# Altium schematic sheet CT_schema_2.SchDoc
size 379 x 215 mm
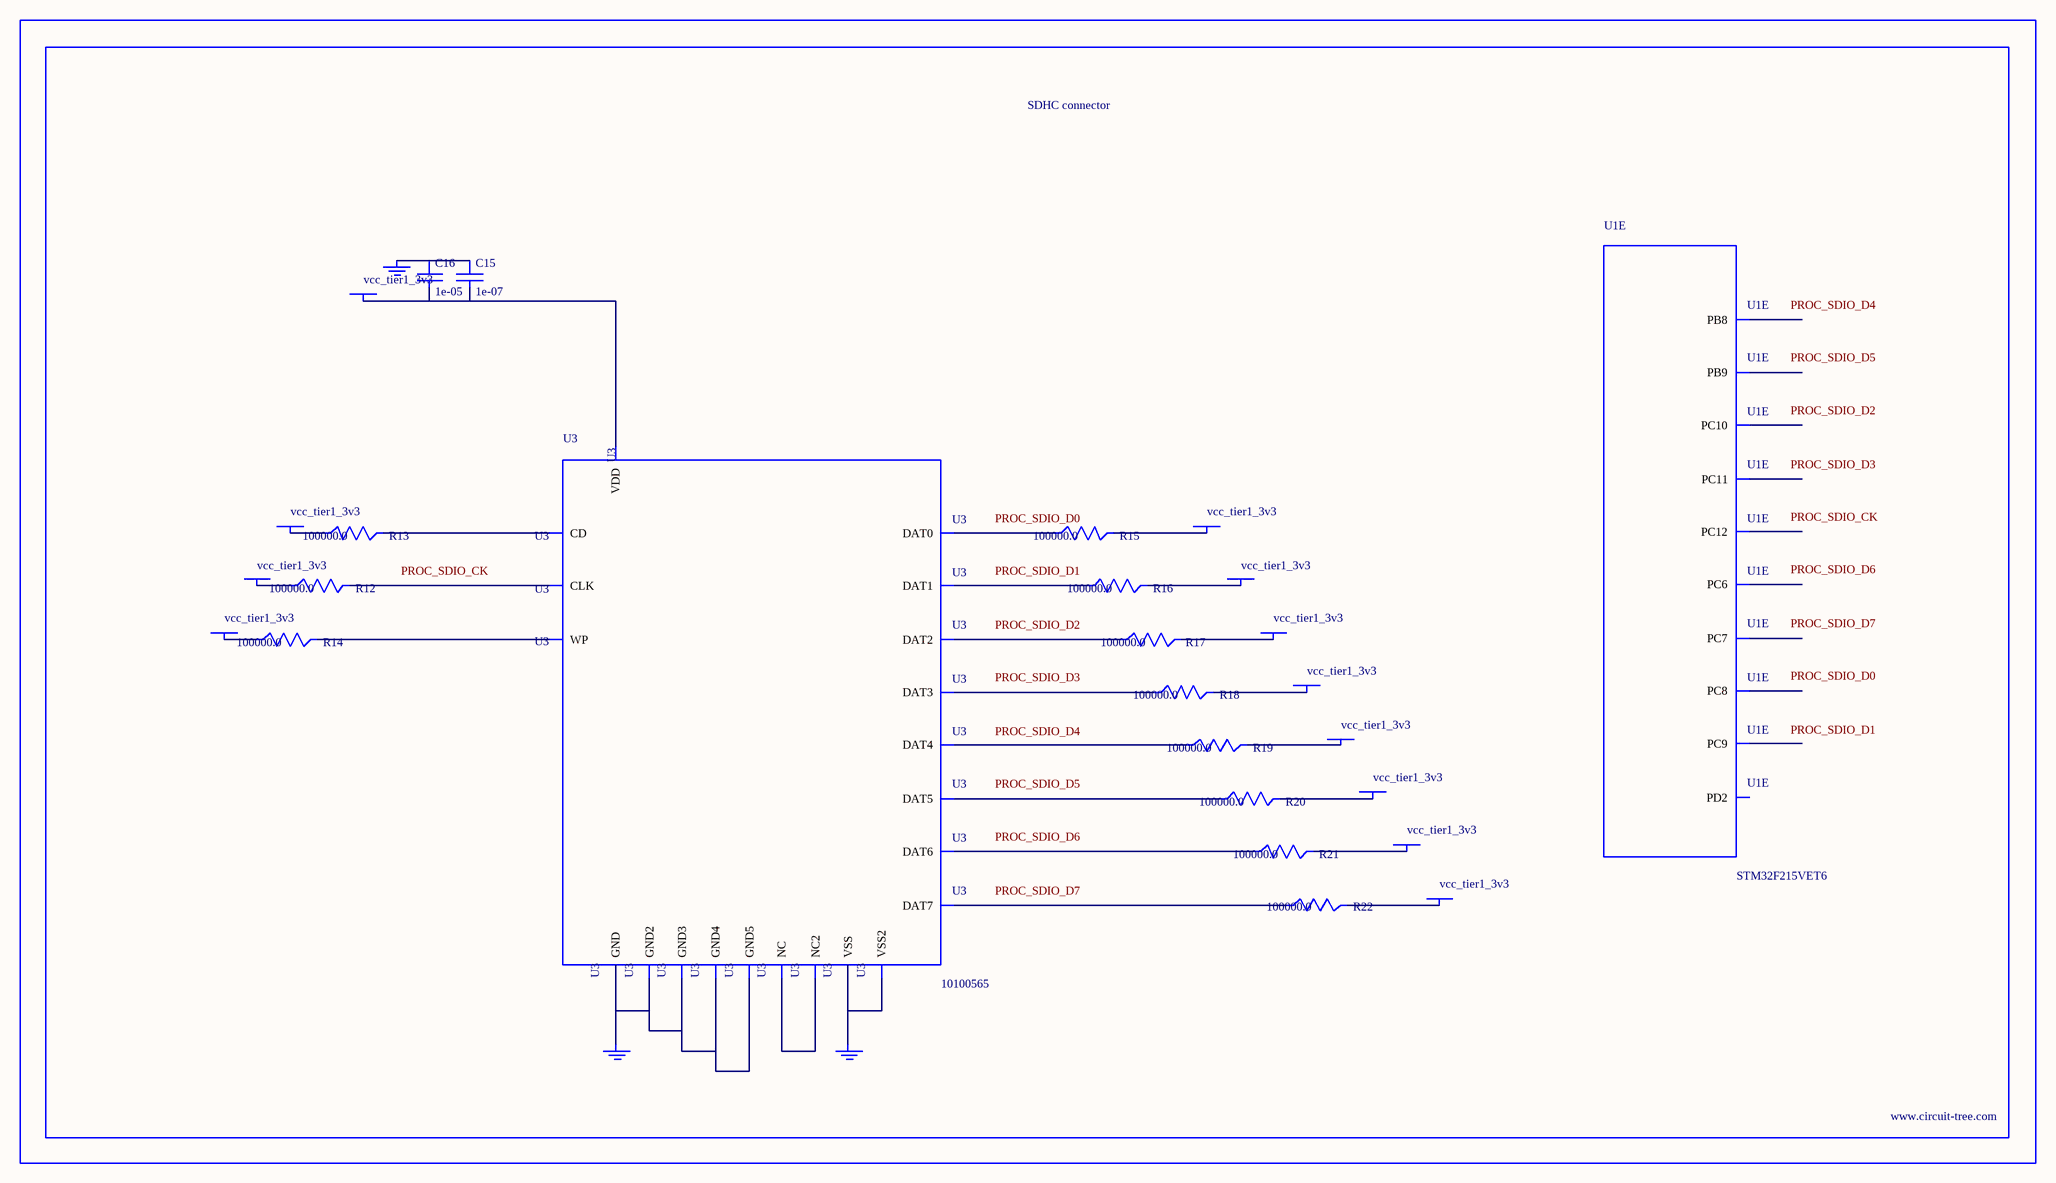
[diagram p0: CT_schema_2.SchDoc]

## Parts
BORDER1  (no value)
C15  1e-07  [C0402]
C16  1e-05  [C0805]
GND_INSTANCE_1_0  (no value)
GND_INSTANCE_1_1  (no value)
GND_INSTANCE_1_2  (no value)
POWER_INSTANCE_1_0  vcc_tier1_3v3
POWER_INSTANCE_1_1  vcc_tier1_3v3
POWER_INSTANCE_1_2  vcc_tier1_3v3
POWER_INSTANCE_1_3  vcc_tier1_3v3
POWER_INSTANCE_1_4  vcc_tier1_3v3
POWER_INSTANCE_1_5  vcc_tier1_3v3
POWER_INSTANCE_1_6  vcc_tier1_3v3
POWER_INSTANCE_1_7  vcc_tier1_3v3
POWER_INSTANCE_1_8  vcc_tier1_3v3
POWER_INSTANCE_1_9  vcc_tier1_3v3
POWER_INSTANCE_1_10  vcc_tier1_3v3
POWER_INSTANCE_1_11  vcc_tier1_3v3
R12  100000.0  [R0603]
R13  100000.0  [R0603]
R14  100000.0  [R0603]
R15  100000.0  [R0603]
R16  100000.0  [R0603]
R17  100000.0  [R0603]
R18  100000.0  [R0603]
R19  100000.0  [R0603]
R20  100000.0  [R0603]
R21  100000.0  [R0603]
R22  100000.0  [R0603]
U1  STM32F215VET6  [LQFP100]  (part E of 9)
U3  10100565  [10100565]

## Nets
NetC15_1: C15.1 C16.1 GND_INSTANCE_1_0.0(GND)
NetC15_2: C15.2 C16.2 POWER_INSTANCE_1_7.0(PWR) U3.9(VDD)
NetGND_INSTANCE_1_1_0: GND_INSTANCE_1_1.0(GND) U3.6(VSS) U3.10(VSS2)
NetGND_INSTANCE_1_2_0: GND_INSTANCE_1_2.0(GND) U3.12(GND) U3.16(GND2) U3.17(GND3) U3.20(GND4) U3.21(GND5)
NetPOWER_INSTANCE_1_0_0: POWER_INSTANCE_1_0.0(PWR) R14.1
NetPOWER_INSTANCE_1_1_0: POWER_INSTANCE_1_1.0(PWR) R13.1
NetPOWER_INSTANCE_1_2_0: POWER_INSTANCE_1_2.0(PWR) R16.2
NetPOWER_INSTANCE_1_3_0: POWER_INSTANCE_1_3.0(PWR) R15.2
NetPOWER_INSTANCE_1_4_0: POWER_INSTANCE_1_4.0(PWR) R22.2
NetPOWER_INSTANCE_1_5_0: POWER_INSTANCE_1_5.0(PWR) R21.2
NetPOWER_INSTANCE_1_6_0: POWER_INSTANCE_1_6.0(PWR) R12.1
NetPOWER_INSTANCE_1_8_0: POWER_INSTANCE_1_8.0(PWR) R20.2
NetPOWER_INSTANCE_1_9_0: POWER_INSTANCE_1_9.0(PWR) R19.2
NetPOWER_INSTANCE_1_10_0: POWER_INSTANCE_1_10.0(PWR) R18.2
NetPOWER_INSTANCE_1_11_0: POWER_INSTANCE_1_11.0(PWR) R17.2
NetR12_2: R12.2 U3.8(CLK)
NetR13_2: R13.2 U3.2(CD)
NetR14_2: R14.2 U3.1(WP)
NetR15_1: R15.1 U3.4(DAT0)
NetR16_1: R16.1 U3.3(DAT1)
NetR17_1: R17.1 U3.15(DAT2)
NetR18_1: R18.1 U3.14(DAT3)
NetR19_1: R19.1 U3.13(DAT4)
NetR20_1: R20.1 U3.11(DAT5)
NetR21_1: R21.1 U3.7(DAT6)
NetR22_1: R22.1 U3.5(DAT7)
NetU3_18: U3.18(NC) U3.19(NC2)

Not connected (* = marked no-connect by the designer): U1 63(PC6) 64(PC7) 65(PC8) 66(PC9) 78(PC10) 79(PC11) 80(PC12) 83(PD2) 95(PB8) 96(PB9)

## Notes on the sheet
- Labels drawn without touching a wire or pin: PROC_SDIO_CK, PROC_SDIO_D0, PROC_SDIO_D1, PROC_SDIO_D2, PROC_SDIO_D3, PROC_SDIO_D4, PROC_SDIO_D5, PROC_SDIO_D6, PROC_SDIO_D7

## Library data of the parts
BORDER1 = BORDER_PAGE1
C15 = C0402C104K3RACTU
C16 = C0805C106K8RACTU
GND_INSTANCE_1_0-GND_INSTANCE_1_2 = GND
POWER_INSTANCE_1_0-POWER_INSTANCE_1_11 = PWR
R12-R22 = RC0603JR-07100KL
